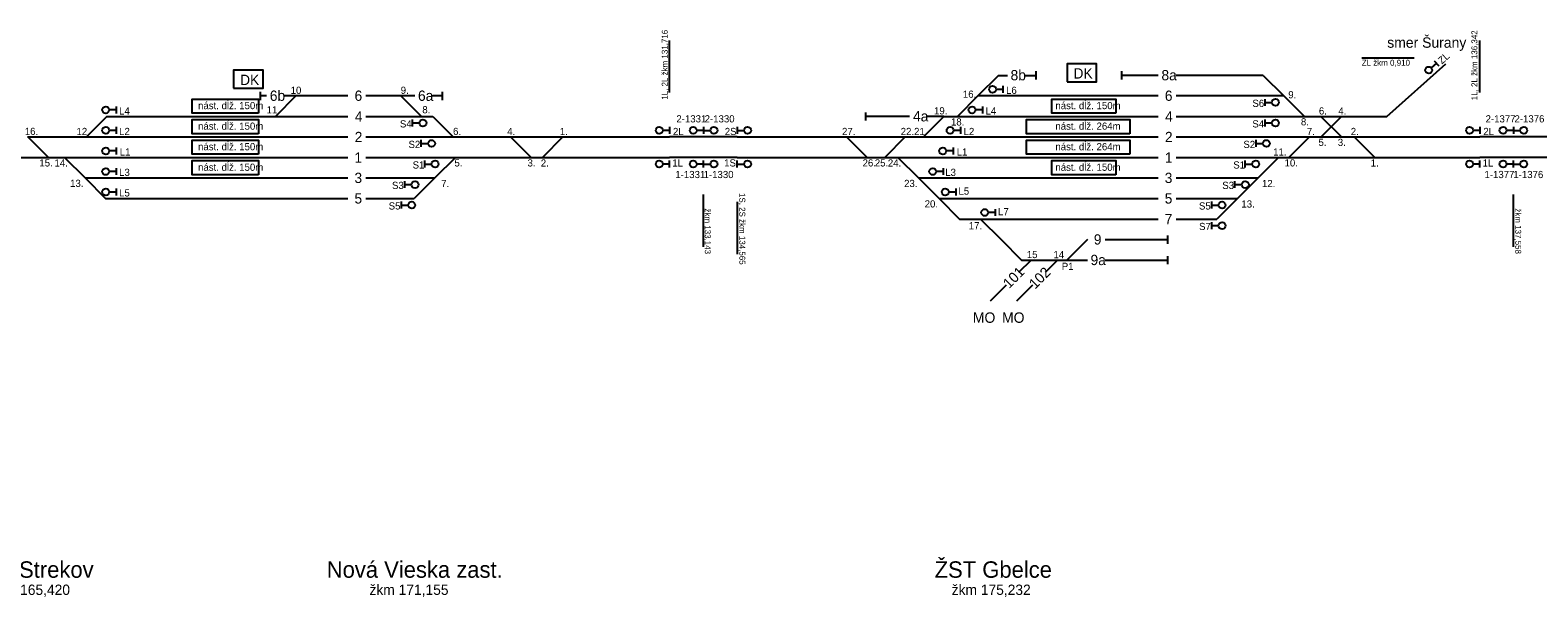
# Model space of a CAD drawing. Extents: x -119 to 851, y -238 to 59.
# Drawn here: x 243.9 to 390.6, y -152.1 to -96.9 of the extents above; entities that cross this region are included whole.
import ezdxf

# ---------------------------------------------------------------- set-up
doc = ezdxf.new("R2010")
doc.units = 0
for name, color, linetype in [('budova', 7, 'Continuous'), ('Level 2', 7, 'Continuous'), ('nastupistia', 7, 'Continuous'), ('netlač', 7, 'Continuous'), ('popisky navestidla', 7, 'Continuous'), ('popisky stanic a zastavok', 7, 'Continuous'), ('PU_navestidla', 7, 'Continuous'), ('PU_oznacenie navestidiel', 7, 'Continuous'), ('PU_stan_kolaje', 7, 'Continuous'), ('PU_vlecky', 7, 'Continuous')]:
    doc.layers.add(name, color=color, linetype=linetype)

msp = doc.modelspace()

# ---------------------------------------------------------------- linework, layer by layer
at = {"layer": 'budova'}
for points in [[(263.73, -102.55), (266.6, -102.55), (266.6, -100.8), (263.73, -100.8)], [(344.82, -101.93), (347.69, -101.93), (347.69, -100.18), (344.82, -100.18)]]:
    msp.add_lwpolyline(points, close=True, dxfattribs=at)
at = {"layer": 'Level 2'}
for p, q in [((341.82, -101.71), (341.82, -100.91)), ((350.15, -101.71), (350.15, -100.91)), ((266.34, -103.71), (266.34, -102.91)), ((266.94, -103.31), (266.34, -103.31)), ((274.86, -103.31), (269.79, -103.31)), ((280.01, -103.31), (276.59, -103.31)), ((281.36, -103.31), (280.01, -103.31)), ((284.07, -103.31), (283.08, -103.31)), ((284.07, -103.71), (284.07, -102.91)), ((353.7, -103.31), (336.16, -103.31)), ((365.92, -103.31), (355.43, -103.31)), ((251.41, -105.31), (274.86, -105.31)), ((276.59, -105.31), (283.1, -105.31)), ((325.23, -105.71), (325.23, -104.91)), ((329.5, -105.31), (325.23, -105.31)), ((332.85, -105.31), (331.22, -105.31)), ((332.85, -105.31), (353.7, -105.31)), ((355.43, -105.31), (364.7, -105.31)), ((243.69, -107.3), (259.89, -107.3)), ((259.89, -107.3), (274.86, -107.3)), ((276.59, -107.3), (283.48, -107.3)), ((283.48, -107.3), (306.15, -107.3)), ((312.74, -107.3), (322.53, -107.3)), ((322.53, -107.3), (338.73, -107.3)), ((338.73, -107.3), (353.7, -107.3)), ((355.43, -107.3), (362.33, -107.3)), ((362.33, -107.3), (385, -107.3)), ((233.89, -109.3), (258.69, -109.3)), ((258.69, -109.3), (274.86, -109.3)), ((276.59, -109.3), (284.48, -109.3)), ((284.48, -109.3), (302.78, -109.3)), ((302.78, -109.3), (306.15, -109.3)), ((312.74, -109.3), (337.53, -109.3)), ((337.53, -109.3), (353.7, -109.3)), ((355.43, -109.3), (363.33, -109.3)), ((363.33, -109.3), (381.62, -109.3)), ((381.62, -109.3), (385, -109.3)), ((249.28, -111.3), (274.86, -111.3)), ((276.59, -111.3), (283.31, -111.3)), ((330.37, -111.3), (353.7, -111.3)), ((355.43, -111.3), (363.41, -111.3)), ((276.59, -113.3), (281.31, -113.3)), ((355.43, -113.3), (361.41, -113.3)), ((355.43, -115.3), (359.41, -115.3)), ((354.63, -117.7), (354.63, -116.9)), ((354.63, -119.69), (354.63, -118.9))]:
    msp.add_line(p, q, dxfattribs=at)
at = {"layer": 'nastupistia'}
for points in [[(266.15, -104.99), (259.69, -104.99), (259.69, -103.61), (266.15, -103.61)], [(349.57, -104.99), (343.36, -104.99), (343.36, -103.61), (349.57, -103.61)], [(266.15, -106.99), (259.69, -106.99), (259.69, -105.61), (266.15, -105.61)], [(350.93, -106.99), (340.89, -106.99), (340.89, -105.61), (350.93, -105.61)], [(266.15, -108.99), (259.69, -108.99), (259.69, -107.61), (266.15, -107.61)], [(350.93, -108.99), (340.89, -108.99), (340.89, -107.61), (350.93, -107.61)], [(266.15, -110.99), (259.69, -110.99), (259.69, -109.61), (266.15, -109.61)], [(349.57, -110.99), (343.36, -110.99), (343.36, -109.61), (349.57, -109.61)]]:
    msp.add_lwpolyline(points, close=True, dxfattribs=at)
at = {"layer": 'netlač'}
for p, q in [((338.15, -101.31), (339.02, -101.31)), ((340.74, -101.31), (341.82, -101.31)), ((353.7, -101.31), (350.15, -101.31)), ((363.92, -101.31), (355.43, -101.31)), ((269.79, -103.31), (268.66, -103.31)), ((312.74, -107.3), (306.15, -107.3)), ((421.04, -107.3), (385, -107.3)), ((312.74, -109.3), (306.15, -109.3)), ((421.04, -109.3), (385, -109.3)), ((251.28, -113.3), (274.86, -113.3)), ((332.37, -113.3), (353.7, -113.3)), ((334.37, -115.3), (353.7, -115.3)), ((348.53, -117.3), (354.63, -117.3)), ((340.4, -119.29), (346.8, -119.29)), ((348.53, -119.29), (354.63, -119.29))]:
    msp.add_line(p, q, dxfattribs=at)
msp.add_lwpolyline([(364.7, -105.31), (375.94, -105.31), (381.67, -100.18)], dxfattribs=at)
at = {"layer": 'popisky navestidla'}
for p, q in [((306.15, -102.99), (306.15, -97.9)), ((385, -102.99), (385, -97.9)), ((378.61, -99.64), (373.51, -99.64)), ((309.43, -112.9), (309.43, -118)), ((388.22, -112.9), (388.22, -118)), ((312.74, -113.62), (312.74, -118.71))]:
    msp.add_line(p, q, dxfattribs=at)
at = {"layer": 'PU_navestidla'}
for p, q in [((380.77, -100.13), (380.27, -100.58)), ((380.55, -99.88), (381, -100.38)), ((338.59, -102.67), (337.91, -102.67)), ((338.59, -102.34), (338.59, -103.01)), ((364.09, -104.28), (364.09, -103.61)), ((364.09, -103.94), (364.77, -103.94)), ((252.29, -104.67), (251.62, -104.67)), ((252.29, -104.33), (252.29, -105.01)), ((281.14, -106.28), (281.14, -105.61)), ((336.59, -104.67), (335.92, -104.67)), ((336.59, -104.34), (336.59, -105.01)), ((364.09, -106.28), (364.09, -105.61)), ((252.29, -106.67), (251.62, -106.67)), ((252.29, -106.33), (252.29, -107)), ((281.14, -105.94), (281.81, -105.94)), ((306.15, -106.67), (305.48, -106.67)), ((306.15, -106.33), (306.15, -107)), ((309.46, -106.67), (308.79, -106.67)), ((309.46, -106.33), (309.46, -107.01)), ((309.46, -106.33), (309.46, -107.01)), ((309.46, -106.67), (310.13, -106.67)), ((312.74, -106.33), (312.74, -107)), ((312.74, -106.67), (313.41, -106.67)), ((334.46, -106.67), (333.79, -106.67)), ((334.46, -106.33), (334.46, -107)), ((364.09, -105.94), (364.77, -105.94)), ((385, -106.67), (384.32, -106.67)), ((385, -106.33), (385, -107)), ((388.25, -106.67), (387.58, -106.67)), ((388.25, -106.33), (388.25, -107.01)), ((388.25, -106.33), (388.25, -107.01)), ((388.25, -106.67), (388.93, -106.67)), ((252.29, -108.33), (252.29, -109)), ((281.98, -108.28), (281.98, -107.6)), ((281.98, -107.94), (282.65, -107.94)), ((333.74, -108.33), (333.74, -109)), ((363.21, -108.28), (363.21, -107.6)), ((363.21, -107.94), (363.88, -107.94)), ((252.29, -108.67), (251.62, -108.67)), ((282.33, -110.28), (282.33, -109.6)), ((282.33, -109.94), (283, -109.94)), ((306.15, -109.94), (305.48, -109.94)), ((306.15, -110.28), (306.15, -109.6)), ((309.46, -109.94), (308.79, -109.94)), ((309.46, -110.28), (309.46, -109.6)), ((309.46, -110.28), (309.46, -109.6)), ((309.46, -109.94), (310.13, -109.94)), ((312.74, -110.28), (312.74, -109.61)), ((312.74, -109.94), (313.41, -109.94)), ((333.74, -108.67), (333.06, -108.67)), ((362.17, -110.28), (362.17, -109.6)), ((362.17, -109.94), (362.85, -109.94)), ((385, -109.94), (384.32, -109.94)), ((385, -110.28), (385, -109.6)), ((388.25, -109.94), (387.58, -109.94)), ((388.25, -110.28), (388.25, -109.6)), ((388.25, -110.28), (388.25, -109.6)), ((388.25, -109.94), (388.93, -109.94)), ((252.29, -110.67), (251.62, -110.67)), ((252.29, -110.33), (252.29, -111)), ((332.76, -110.67), (332.09, -110.67)), ((332.76, -110.33), (332.76, -111)), ((252.29, -112.67), (251.62, -112.67)), ((252.29, -112.33), (252.29, -113)), ((280.38, -112.27), (280.38, -111.6)), ((280.38, -111.94), (281.05, -111.94)), ((333.99, -112.67), (333.32, -112.67)), ((333.99, -112.33), (333.99, -113)), ((361.16, -112.27), (361.16, -111.6)), ((361.16, -111.94), (361.83, -111.94)), ((280.06, -114.27), (280.06, -113.6)), ((280.06, -113.94), (280.73, -113.94)), ((337.83, -114.32), (337.83, -115)), ((358.9, -114.27), (358.9, -113.6)), ((358.9, -113.94), (359.57, -113.94)), ((337.83, -114.66), (337.16, -114.66)), ((358.9, -116.27), (358.9, -115.6)), ((358.9, -115.94), (359.57, -115.94))]:
    msp.add_line(p, q, dxfattribs=at)
for centre in [(380.02, -100.8), (337.58, -102.67), (365.1, -103.94), (251.29, -104.67), (282.15, -105.94), (335.58, -104.67), (365.1, -105.94), (251.29, -106.67), (305.15, -106.67), (308.45, -106.67), (310.47, -106.67), (313.74, -106.67), (333.45, -106.67), (383.99, -106.67), (387.25, -106.67), (389.26, -106.67), (251.29, -108.67), (282.99, -107.94), (332.73, -108.67), (364.22, -107.94), (283.33, -109.94), (305.15, -109.94), (308.45, -109.94), (310.47, -109.94), (313.74, -109.94), (363.18, -109.94), (383.99, -109.94), (387.25, -109.94), (389.26, -109.94), (251.29, -110.67), (331.76, -110.67), (251.29, -112.66), (281.38, -111.94), (332.98, -112.66), (362.17, -111.94), (281.06, -113.94), (336.82, -114.66), (359.91, -113.94), (359.91, -115.94)]:
    msp.add_circle(centre, 0.336, dxfattribs=at)
at = {"layer": 'PU_stan_kolaje'}
for points in [[(338.15, -101.31), (336.16, -103.31)], [(363.92, -101.31), (365.92, -103.31)], [(269.79, -103.31), (267.79, -105.31)], [(280.01, -103.31), (282.01, -105.31)], [(336.16, -103.31), (334.16, -105.31)], [(365.92, -103.31), (367.92, -105.31)], [(251.41, -105.31), (249.41, -107.3)], [(283.1, -105.31), (285.1, -107.3)], [(332.85, -105.31), (330.85, -107.3)], [(369.52, -105.31), (371.52, -107.3)], [(371.54, -105.31), (369.54, -107.3)], [(243.71, -107.3), (245.71, -109.3)], [(290.67, -107.3), (292.67, -109.3)], [(295.77, -107.3), (293.77, -109.3)], [(323.37, -107.3), (325.37, -109.3)], [(329.08, -107.3), (327.08, -109.3)], [(368.42, -107.3), (366.42, -109.3)], [(372.76, -107.3), (374.76, -109.3)], [(247.28, -109.3), (249.28, -111.3)], [(285.31, -109.3), (283.31, -111.3)], [(328.37, -109.3), (330.37, -111.3)], [(365.4, -109.3), (363.41, -111.3)], [(249.28, -111.3), (251.28, -113.3)], [(283.31, -111.3), (281.31, -113.3)], [(330.37, -111.3), (332.37, -113.3)], [(363.41, -111.3), (361.41, -113.3)], [(332.37, -113.3), (334.37, -115.3)], [(361.41, -113.3), (359.41, -115.3)], [(336.4, -115.3), (338.4, -117.3)], [(338.4, -117.3), (340.4, -119.29)], [(346.8, -117.3), (344.8, -119.3)], [(341.32, -119.29), (340.11, -120.51)], [(343.9, -119.29), (342.69, -120.51)], [(338.89, -121.73), (337.33, -123.29)], [(341.47, -121.73), (339.91, -123.29)]]:
    msp.add_lwpolyline(points, dxfattribs=at)

# ---------------------------------------------------------------- texts
at = {"layer": 'budova'}
for p in [(345.45, -101.62), (264.36, -102.25)]:
    msp.add_text('DK', height=1.004, dxfattribs=at).set_placement(p)
at = {"layer": 'nastupistia'}
for s, p in [('nást. dĺž. 150m', (260.27, -104.6)), ('nást. dĺž. 150m', (343.69, -104.6)), ('nást. dĺž. 150m', (260.27, -106.6)), ('nást. dĺž. 264m', (343.69, -106.6)), ('nást. dĺž. 150m', (260.27, -108.6)), ('nást. dĺž. 264m', (343.69, -108.6)), ('nást. dĺž. 150m', (260.27, -110.6)), ('nást. dĺž. 150m', (343.69, -110.6))]:
    msp.add_text(s, height=0.7, dxfattribs=at).set_placement(p)
at = {"layer": 'popisky navestidla'}
for s, rotation, p in [('1L, 2L žkm 131,716', 90, (305.97, -103.68)), ('1L, 2L žkm 136,342', 90, (384.75, -103.73)), ('1S, 2S žkm 134,565', 270, (312.94, -112.76)), ('žkm 133,143', 270, (309.58, -114.27)), ('žkm 137,558', 270, (388.43, -114.26))]:
    msp.add_text(s, height=0.5793, rotation=rotation, dxfattribs=at).set_placement(p)
msp.add_text('ZL žkm 0,910', height=0.5793, dxfattribs=at).set_placement((373.5, -100.37))
at = {"layer": 'popisky stanic a zastavok'}
for s, height, p in [('ŽST Strekov', 1.6, (238.22, -150.22)), ('Nová Vieska zast.', 1.6, (272.79, -150.22)), ('ŽST Gbelce', 1.6, (331.94, -150.22)), ('žkm 165,420', 1.0044, (240.12, -151.89)), ('žkm 171,155', 1.0044, (276.95, -151.89)), ('žkm 175,232', 1.0044, (333.6, -151.89))]:
    msp.add_text(s, height=height, dxfattribs=at).set_placement(p)
at = {"layer": 'PU_oznacenie navestidiel'}
msp.add_text('ZL', height=0.7, rotation=41.7909, dxfattribs=at).set_placement((381.3, -100.26))
for s, p in [('10', (269.28, -103.11)), ('9.', (279.99, -103.11)), ('L6', (338.89, -103.11)), ('16.', (334.69, -103.49)), ('S6', (362.86, -104.38)), ('9.', (366.35, -103.54)), ('L4', (252.59, -105.12)), ('11', (266.94, -105.02)), ('8.', (282.09, -105)), ('2-1331', (306.81, -105.89)), ('2-1330', (309.56, -105.89)), ('19.', (331.88, -105.11)), ('18.', (333.53, -106.19)), ('L4', (336.89, -105.12)), ('8.', (367.58, -106.18)), ('6.', (369.33, -105.12)), ('4.', (371.22, -105.13)), ('2-1377', (385.55, -105.89)), ('2-1376', (388.36, -105.89)), ('16.', (243.41, -107.11)), ('12.', (248.44, -107.12)), ('L2', (252.59, -107.12)), ('S4', (279.91, -106.38)), ('6.', (285.08, -107.11)), ('4.', (290.35, -107.12)), ('1.', (295.47, -107.12)), ('2L', (306.48, -107.12)), ('2S', (311.52, -107.12)), ('27.', (322.93, -107.12)), ('22.', (328.64, -107.12)), ('21.', (329.94, -107.12)), ('L2', (334.76, -107.12)), ('S4', (362.86, -106.38)), ('7.', (368.16, -107.12)), ('2.', (372.43, -107.12)), ('2L', (385.33, -107.12)), ('L1', (252.65, -109.12)), ('S2', (280.75, -108.38)), ('L1', (334.09, -109.12)), ('S2', (361.98, -108.38)), ('11.', (364.88, -109.12)), ('5.', (369.29, -108.18)), ('3.', (371.17, -108.18)), ('15.', (244.83, -110.18)), ('14.', (246.3, -110.19)), ('S1', (281.15, -110.38)), ('5.', (285.22, -110.18)), ('3.', (292.33, -110.18)), ('2.', (293.62, -110.19)), ('1L', (306.42, -110.19)), ('1S', (311.46, -110.18)), ('26.', (324.93, -110.18)), ('25.', (326.12, -110.18)), ('24.', (327.39, -110.19)), ('S1', (361, -110.38)), ('10.', (365.99, -110.18)), ('1.', (374.37, -110.19)), ('1L', (385.26, -110.19)), ('13.', (247.82, -112.17)), ('L3', (252.59, -111.1)), ('7.', (283.93, -112.19)), ('1-1331', (306.71, -111.31)), ('1-1330', (309.46, -111.31)), ('23.', (328.97, -112.18)), ('L3', (332.97, -111.1)), ('12.', (363.79, -112.19)), ('1-1377', (385.44, -111.31)), ('1-1376', (388.25, -111.31)), ('L5', (252.59, -113.1)), ('S3', (279.14, -112.37)), ('L5', (334.26, -112.92)), ('S3', (359.93, -112.37)), ('S5', (278.82, -114.37)), ('20.', (330.97, -114.17)), ('L7', (338.11, -114.93)), ('S5', (357.66, -114.37)), ('13.', (361.79, -114.18)), ('17.', (335.26, -116.3)), ('S7', (357.67, -116.37)), ('15', (340.91, -119.1)), ('14', (343.5, -119.11)), ('P1', (344.31, -120.25))]:
    msp.add_text(s, height=0.7, dxfattribs=at).set_placement(p)
at = {"layer": 'PU_stan_kolaje'}
for s, height, p in [('8b', 1.004, (339.33, -101.79)), ('8a', 1.004, (354.01, -101.79)), ('6b', 1.004, (267.25, -103.79)), ('6', 1, (275.5, -103.79)), ('6a', 1.004, (281.67, -103.79)), ('6', 1, (354.34, -103.79)), ('4', 1, (275.53, -105.81)), ('4a', 1.004, (329.84, -105.79)), ('4', 1, (354.37, -105.81)), ('2', 1, (275.51, -107.81)), ('2', 1, (354.35, -107.81)), ('1', 1, (275.49, -109.81)), ('1', 1, (354.34, -109.81)), ('3', 1, (275.49, -111.79)), ('3', 1, (354.33, -111.79)), ('5', 1, (275.49, -113.79)), ('5', 1, (354.33, -113.79)), ('7', 1, (354.33, -115.8)), ('9', 1, (347.43, -117.78)), ('9a', 1.004, (347.11, -119.78))]:
    msp.add_text(s, height=height, dxfattribs=at).set_placement(p)
for s, p in [('101', (339.19, -122.12)), ('102', (341.72, -122.17))]:
    msp.add_text(s, height=1.004, rotation=45, dxfattribs=at).set_placement(p)
at = {"layer": 'PU_vlecky'}
for s, p in [('smer Šurany', (375.98, -98.62)), ('MO', (335.66, -125.4)), ('MO', (338.5, -125.4))]:
    msp.add_text(s, height=1.015, dxfattribs=at).set_placement(p)

doc.saveas('drawing.dxf')
